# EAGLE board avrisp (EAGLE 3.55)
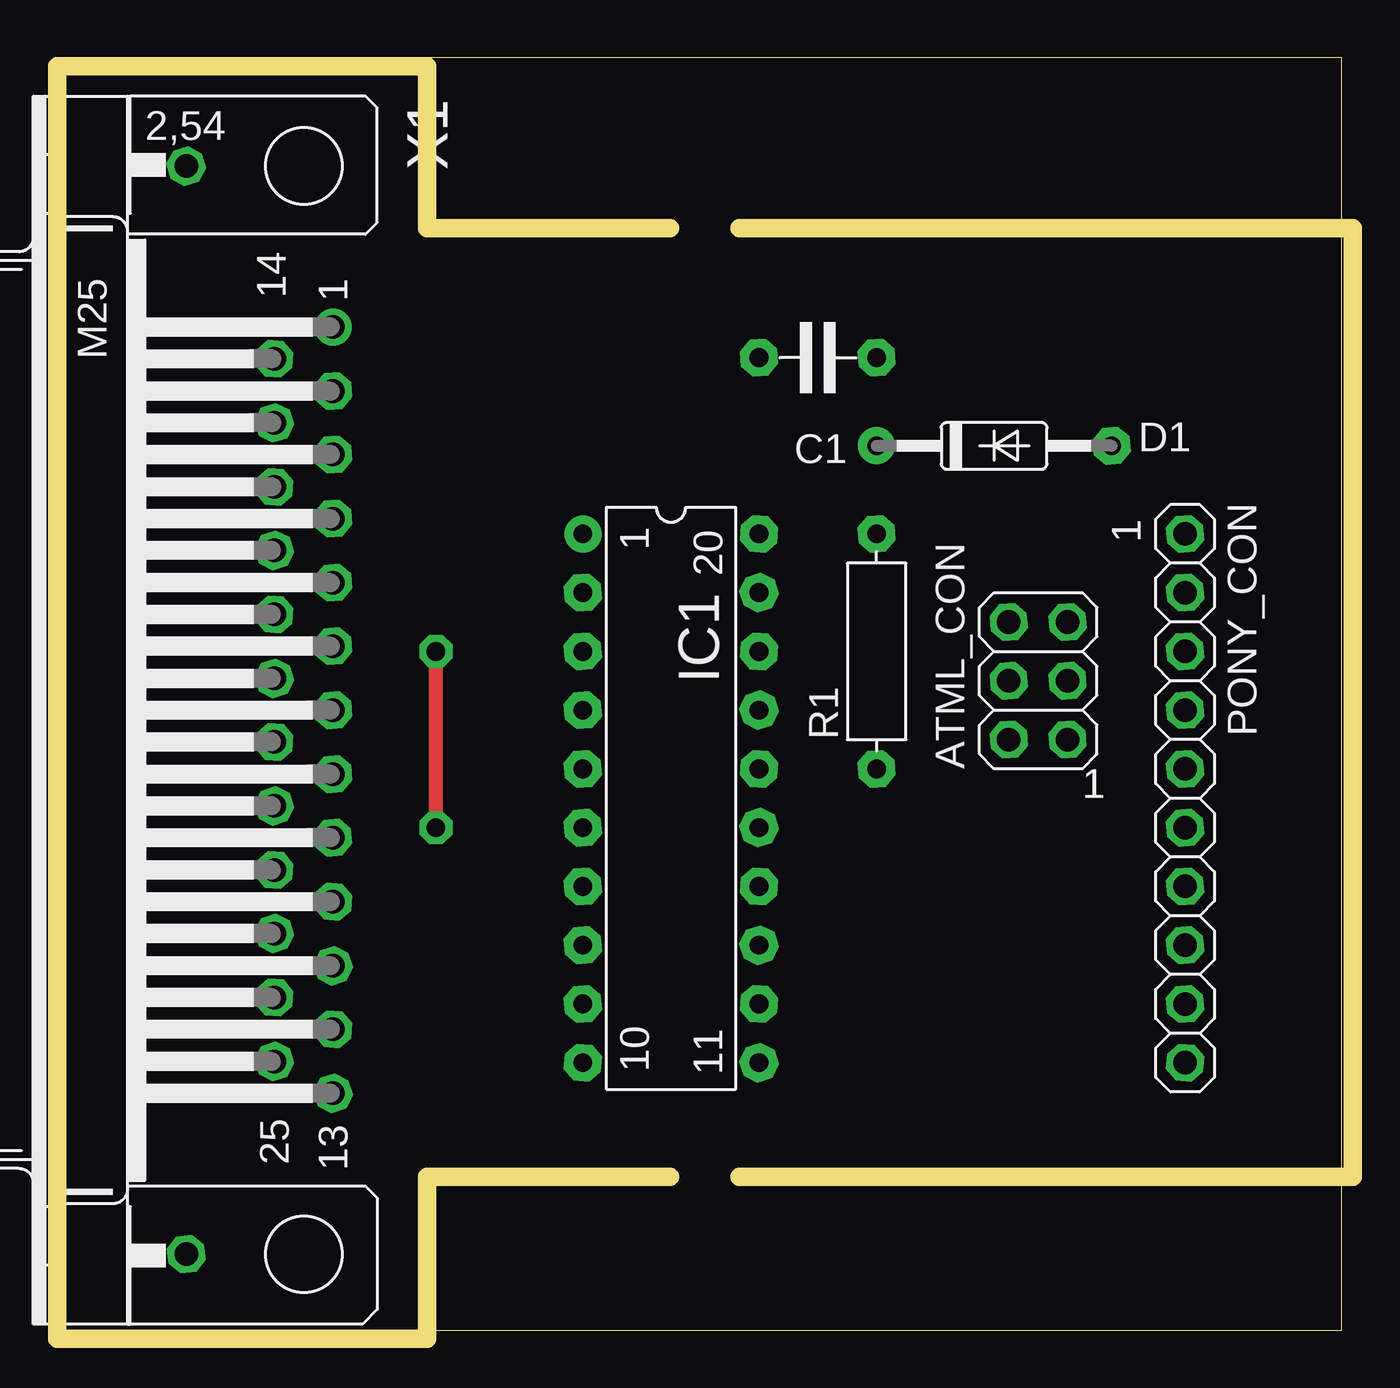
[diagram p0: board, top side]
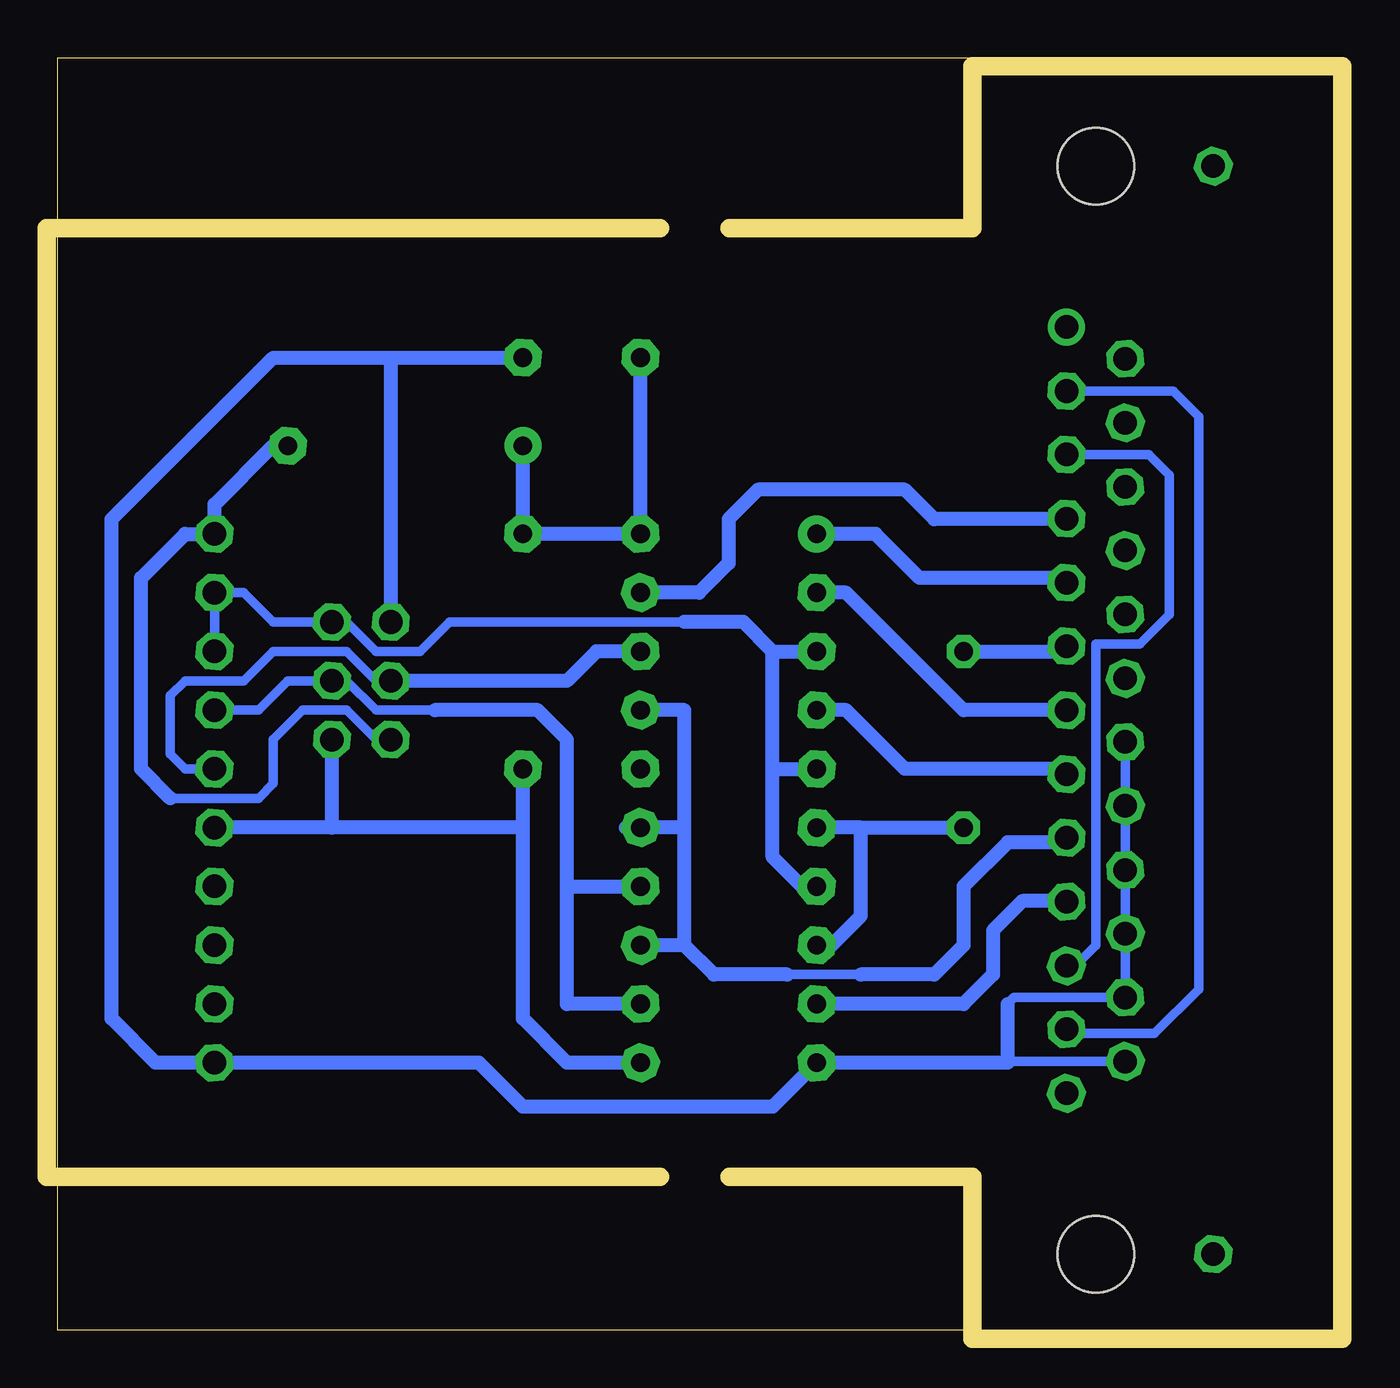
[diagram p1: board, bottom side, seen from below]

Size 55.5 x 55 mm. Coordinates in mm from the lower left corner, seen from the top.
Outline: 0,0 55.5,0 55.5,55 0,55 0,0
Copper layers used: Top, Bottom
Milling: 10 lines

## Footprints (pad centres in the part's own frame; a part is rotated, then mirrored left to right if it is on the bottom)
03 = drill 1.016 pad 1.6 octagon:  -2.54,-1.27;  -2.54,1.27;  0,-1.27;  0,1.27;  2.54,-1.27;  2.54,1.27
5 = drill 0.813 pad 1.6 octagon:  -2.54,0;  2.54,0
35-10 = drill 0.813 pad 1.6 round:  -5.08,0 | drill 0.813 pad 1.6 octagon:  5.08,0
L20 = drill 0.813 pad 1.6 round:  -11.43,-3.81 | drill 0.813 pad 1.6 octagon:  -8.89,-3.81;  -6.35,-3.81;  -3.81,-3.81;  -1.27,-3.81;  1.27,-3.81;  3.81,-3.81;  6.35,-3.81;  8.89,-3.81;  11.43,-3.81;  11.43,3.81;  8.89,3.81;  6.35,3.81;  3.81,3.81;  1.27,3.81;  -1.27,3.81;  -3.81,3.81;  -6.35,3.81;  -8.89,3.81;  -11.43,3.81
10 = drill 1.016 pad 1.6 octagon:  -11.43,0;  -8.89,0;  -6.35,0;  -3.81,0;  -1.27,0;  1.27,0;  3.81,0;  6.35,0;  8.89,0;  11.43,0
10' = drill 0.813 pad 1.6 octagon:  -5.08,0;  5.08,0
5H = drill 1.016 pad 1.6 octagon:  16.561,1.27;  13.792,1.27;  11.049,1.27;  8.28,1.27;  5.512,1.27;  2.769,1.27;  0,1.27;  -2.769,1.27;  -5.512,1.27;  -8.28,1.27;  -11.049,1.27;  -13.792,1.27;  15.189,-1.27;  12.421,-1.27;  9.652,-1.27;  6.909,-1.27;  4.14,-1.27;  1.372,-1.27;  -1.372,-1.27;  -4.14,-1.27;  -6.909,-1.27;  -9.652,-1.27;  -12.421,-1.27;  -15.189,-1.27;  23.52,-5.08;  -23.52,-5.08 | drill 1.016 pad 1.6 round:  -16.561,1.27 | hole 3.302: 23.52,0; -23.52,0

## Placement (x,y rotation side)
ATML_CON  PINHD-2X3  [03]  42.38,28.07 90 top
C1  100nF  [5]  32.85,42.04 180 top
D1  1N4148  [35-10]  40.48,38.23 0 top
IC1  74244  [L20]  26.5,22.99 270 top
PONY_CON  PINHD-1X10  [10]  48.73,22.99 270 top
R1  100K  [10']  35.39,29.34 90 top
X1  M25H  [5H]  10.63,26.8 270 top

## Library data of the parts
ATML_CON PONY_CON = PINHEAD
C1 R1 = DISCRETE
D1 = DIODE
IC1 = 74XX
X1 = SUBD-A

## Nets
GND: ATML_CON. C1. IC1. PONY_CON. X1.
MISO: ATML_CON. IC1. PONY_CON. R1.
MOSI: ATML_CON. IC1. PONY_CON.
N$1: X1.
N$2: X1.
N$3: IC1. X1.
N$4: IC1. X1.
N$5: IC1. X1.
N$7: IC1. X1.
N$8: IC1. X1.
N$10: IC1. X1.
N$11: IC1. X1.
RST: ATML_CON. IC1. PONY_CON.
SCK: ATML_CON. IC1. PONY_CON.
VCC: C1. D1. IC1. R1.
VCC/2: ATML_CON. D1. PONY_CON.

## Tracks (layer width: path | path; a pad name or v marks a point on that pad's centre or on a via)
GND
  Bottom 0.406: 9.36,11.61 14.39,11.61 14.44,11.56 | 9.36,14.38 9.36,14.1 | 9.36,17.15 9.36,17.27 | 9.36,14.38 9.36,17.15 | 9.36,19.89 9.36,20.45 | 9.36,17.15 9.36,19.89 | 9.36,19.89 9.36,22.66 9.36,25.43 9.36,25.53 | 9.36,14.38 14.16,14.38 14.44,14.1
  Bottom 0.61: 14.44,14.1 14.44,11.56 22.7,11.56 24.6,9.66 35.39,9.66 37.3,11.56 PONY_CON. 51.27,11.56 53.17,13.47 53.17,35.05 46.19,42.04 41.11,42.04 | 41.11,42.04 35.39,42.04 | 41.11,42.04 ATML_CON.
MISO
  Bottom 0.61: 35.39,21.72 35.39,13.47 33.49,11.56 30.31,11.56 | 43.65,21.72 48.73,21.72 | 35.39,21.72 35.39,24.26 | 35.39,21.72 43.65,21.72 | 43.65,21.72 43.65,25.53
MOSI
  Bottom 0.406: 41.11,28.07 41.74,28.07 43.02,29.34 46.19,29.34 47.46,28.07 50,28.07 50.63,27.43 50.63,24.89 50,24.26 48.73,24.26
  Bottom 0.61: 41.11,28.07 33.49,28.07 32.22,29.34 30.31,29.34
N$1
  Bottom 0.406: 11.9,37.85 8.34,37.85 7.46,36.96 7.46,30.93 8.73,29.66 10.63,29.66 10.63,16.64 11.9,15.37 11.9,15.75
N$2
  Bottom 0.406: 11.9,40.59 7.28,40.59 6.18,39.5 6.18,14.74 8.09,12.83 11.9,12.83 11.9,13.01
N$3
  Bottom 0.61: 30.31,31.88 27.77,31.88 26.5,33.15 26.5,35.05 25.23,36.33 18.88,36.33 17.61,35.05 11.9,35.05 11.9,35.08
N$4
  Bottom 0.61: 22.7,34.42 20.15,34.42 18.25,32.52 11.9,32.52 11.9,32.31
N$5  (via drill 0.81 pad 1.42)
  Top 0.61: v16.34,21.72 v16.34,29.34
  Bottom 0.61: 20.79,21.72 20.79,17.91 22.06,16.64 22.7,16.64 | 20.79,21.72 22.7,21.72 | 20.79,21.72 v16.34,21.72 | 11.9,29.57 11.9,29.34 v16.34,29.34
N$7
  Bottom 0.61: 22.7,31.88 21.42,31.88 16.34,26.8 11.9,26.8
N$8
  Bottom 0.61: 22.7,26.8 21.42,26.8 18.88,24.26 11.9,24.26 11.9,24.03
N$10
  Bottom 0.406: 20.79,15.37 23.96,15.37
  Bottom 0.61: 28.41,16.64 30.31,16.64 | 28.41,16.64 27.14,15.37 23.96,15.37 | 20.79,15.37 17.61,15.37 16.34,16.64 16.34,19.18 14.44,21.08 11.9,21.08 11.9,21.29 11.9,21.4 | 30.31,26.8 28.41,26.8 28.41,21.72 | 30.95,21.72 30.31,21.72 28.41,21.72 | 28.41,16.64 28.41,21.72
N$11
  Bottom 0.61: 22.7,14.1 16.34,14.1 15.08,15.37 15.08,17.27 13.81,18.54 11.9,18.54 11.9,18.52
RST
  Bottom 0.406: 28.41,30.61 38.57,30.61 39.84,29.34 41.74,29.34 43.02,30.61 43.65,30.61 46.19,30.61 47.46,31.88 48.73,31.88 48.73,29.34
  Bottom 0.61: 22.7,19.18 23.33,19.18 24.6,20.45 24.6,24.26 | 24.6,24.26 22.7,24.26 | 24.6,24.26 24.6,29.34 | 24.6,29.34 22.7,29.34 | 24.6,29.34 25.87,30.61 28.41,30.61
SCK
  Bottom 0.406: 39.2,26.8 41.74,26.8 43.02,28.07 43.65,28.07 45.55,28.07 46.82,26.8 48.73,26.8
  Bottom 0.61: 39.2,26.8 34.76,26.8 33.49,25.53 33.49,19.18 | 33.49,19.18 30.31,19.18 | 30.31,14.1 33.49,14.1 33.49,19.18
VCC
  Bottom 0.61: 35.39,38.23 R1. IC1. C1.
VCC/2
  Bottom 0.406: 41.11,25.53 41.74,25.53 43.02,26.8 44.92,26.8 46.19,25.53 46.19,23.62 46.82,22.99 50.63,22.99
  Bottom 0.61: D1. 46.19,38.23 48.73,35.69 48.73,34.42 50,34.42 51.91,32.52 51.91,24.26 50.63,22.99

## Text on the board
tPlace: 1 | 1
bmill: 1 | 1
